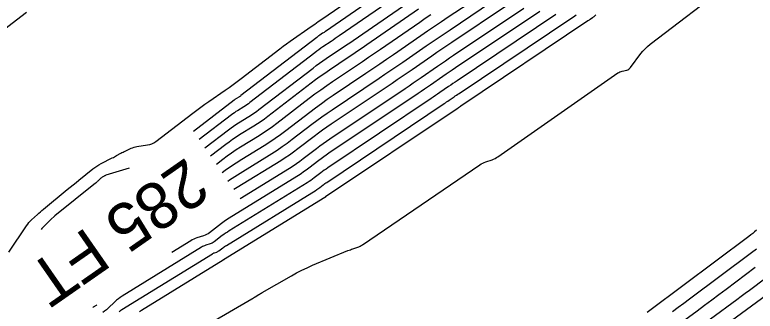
# Model space of a CAD drawing. Extents: x 1768942 to 1774819, y 723037 to 732099.
# Drawn here: x 1770796.8 to 1770891.8, y 726671.9 to 726709.8 of the extents above; entities that cross this region are included whole.
import ezdxf

# ---------------------------------------------------------------- set-up
doc = ezdxf.new("R2010")
doc.units = 0
doc.layers.add('R_Contour Annot', color=7, linetype='Continuous')
doc.layers.add('R_Contours', color=7, linetype='Continuous')

msp = doc.modelspace()

# ---------------------------------------------------------------- linework, layer by layer
at = {"layer": 'R_Contours'}
for points in [[(1770848.202, 726715.686), (1770836.674, 726707.725), (1770836.581, 726707.66), (1770836.487, 726707.597), (1770836.394, 726707.533), (1770836.3, 726707.47), (1770835.923, 726707.218), (1770835.829, 726707.154), (1770835.737, 726707.089), (1770835.645, 726707.022), (1770835.555, 726706.954), (1770825.81, 726699.484), (1770825.742, 726699.433), (1770825.673, 726699.385), (1770825.603, 726699.338), (1770825.531, 726699.292), (1770825.243, 726699.115), (1770825.172, 726699.07), (1770825.102, 726699.023), (1770825.033, 726698.974), (1770824.965, 726698.923), (1770819.726, 726694.907)], [(1770817.292, 726667.688), (1770827.207, 726673.444), (1770827.319, 726673.51), (1770827.431, 726673.577), (1770827.542, 726673.645), (1770827.653, 726673.714), (1770828.094, 726673.993), (1770828.204, 726674.063), (1770828.316, 726674.13), (1770828.428, 726674.197), (1770828.541, 726674.263), (1770832.288, 726676.405), (1770832.955, 726676.773), (1770833.633, 726677.12), (1770834.322, 726677.444), (1770835.021, 726677.748), (1770839.55, 726679.627), (1770839.704, 726679.69), (1770839.86, 726679.749), (1770840.017, 726679.805), (1770840.175, 726679.858), (1770840.809, 726680.064), (1770840.965, 726680.12), (1770841.115, 726680.188), (1770841.261, 726680.266), (1770841.401, 726680.354), (1770856.482, 726690.615), (1770856.661, 726690.729), (1770856.846, 726690.829), (1770857.037, 726690.918), (1770857.235, 726690.994), (1770858.039, 726691.273), (1770858.236, 726691.35), (1770858.427, 726691.439), (1770858.611, 726691.541), (1770858.789, 726691.656), (1770874.204, 726702.391), (1770874.329, 726702.47), (1770874.461, 726702.536), (1770874.598, 726702.589), (1770874.74, 726702.629), (1770875.323, 726702.765), (1770875.461, 726702.809), (1770875.586, 726702.875), (1770875.697, 726702.962), (1770875.794, 726703.071), (1770877.148, 726704.866), (1770877.413, 726705.195), (1770877.7, 726705.504), (1770878.006, 726705.793), (1770878.333, 726706.061), (1770888.553, 726713.898)], [(1770848.34, 726713.984), (1770838.439, 726707.145), (1770838.178, 726706.965), (1770837.916, 726706.787), (1770837.654, 726706.609), (1770837.391, 726706.433), (1770836.339, 726705.728), (1770836.077, 726705.55), (1770835.818, 726705.368), (1770835.563, 726705.181), (1770835.31, 726704.991), (1770826.962, 726698.592), (1770826.773, 726698.45), (1770826.58, 726698.314), (1770826.383, 726698.182), (1770826.183, 726698.056), (1770825.377, 726697.559), (1770825.177, 726697.433), (1770824.98, 726697.301), (1770824.787, 726697.164), (1770824.598, 726697.023), (1770820.461, 726693.852)], [(1770796.011, 726679.442), (1770798.302, 726682.824), (1770798.449, 726683.029), (1770798.607, 726683.224), (1770798.776, 726683.41), (1770798.956, 726683.587), (1770799.698, 726684.275), (1770799.885, 726684.445), (1770800.074, 726684.613), (1770800.266, 726684.777), (1770800.461, 726684.939), (1770803.526, 726687.44), (1770803.903, 726687.746), (1770804.279, 726688.052), (1770804.656, 726688.358), (1770805.034, 726688.662), (1770806.8, 726690.087), (1770807.055, 726690.281), (1770807.318, 726690.461), (1770807.591, 726690.627), (1770807.873, 726690.779), (1770809.312, 726691.505), (1770809.451, 726691.577), (1770809.589, 726691.649), (1770809.727, 726691.724), (1770809.863, 726691.8), (1770810.409, 726692.107), (1770810.546, 726692.183), (1770810.684, 726692.255), (1770810.824, 726692.325), (1770810.966, 726692.391), (1770811.735, 726692.742), (1770811.912, 726692.816), (1770812.094, 726692.877), (1770812.279, 726692.924), (1770812.468, 726692.959), (1770813.835, 726693.164), (1770814.119, 726693.225), (1770814.389, 726693.319), (1770814.645, 726693.448), (1770814.886, 726693.61), (1770819.632, 726697.247), (1770820.14, 726697.631), (1770820.652, 726698.009), (1770821.17, 726698.379), (1770821.692, 726698.743), (1770823.792, 726700.184), (1770824.315, 726700.547), (1770824.832, 726700.918), (1770825.345, 726701.295), (1770825.853, 726701.679), (1770830.801, 726705.472), (1770831.24, 726705.804), (1770831.683, 726706.132), (1770832.129, 726706.454), (1770832.579, 726706.771), (1770834.387, 726708.03), (1770834.839, 726708.345), (1770835.291, 726708.659), (1770835.743, 726708.974), (1770836.195, 726709.289), (1770840.941, 726712.591)], [(1770821.196, 726692.796), (1770824.231, 726695.122), (1770824.542, 726695.355), (1770824.859, 726695.579), (1770825.182, 726695.795), (1770825.51, 726696.003), (1770826.835, 726696.819), (1770827.164, 726697.027), (1770827.486, 726697.243), (1770827.804, 726697.467), (1770828.115, 726697.7), (1770835.065, 726703.027), (1770835.48, 726703.34), (1770835.9, 726703.646), (1770836.325, 726703.946), (1770836.754, 726704.238), (1770838.483, 726705.396), (1770838.915, 726705.686), (1770839.345, 726705.977), (1770839.775, 726706.27), (1770840.203, 726706.565), (1770848.479, 726712.281)], [(1770823.402, 726689.625), (1770823.806, 726689.926), (1770824.496, 726690.414), (1770825.197, 726690.884), (1770825.911, 726691.336), (1770828.791, 726693.109), (1770829.505, 726693.561), (1770830.206, 726694.031), (1770830.896, 726694.518), (1770831.573, 726695.024), (1770834.65, 726697.383), (1770835.391, 726697.941), (1770836.141, 726698.488), (1770836.899, 726699.022), (1770837.666, 726699.545), (1770841.866, 726702.356), (1770842.75, 726702.95), (1770843.632, 726703.548), (1770844.512, 726704.148), (1770845.39, 726704.752), (1770848.895, 726707.173), (1770849.773, 726707.777), (1770850.653, 726708.378), (1770851.535, 726708.975), (1770852.419, 726709.57), (1770855.965, 726711.945)], [(1770824.152, 726688.547), (1770824.369, 726688.701), (1770825.028, 726689.142), (1770825.698, 726689.567), (1770829.785, 726692.083), (1770830.458, 726692.509), (1770831.119, 726692.952), (1770831.769, 726693.411), (1770832.407, 726693.888), (1770834.936, 726695.827), (1770835.573, 726696.306), (1770836.216, 726696.775), (1770836.867, 726697.234), (1770837.526, 726697.683), (1770843.538, 726701.707), (1770844.301, 726702.22), (1770845.063, 726702.736), (1770845.822, 726703.255), (1770846.58, 726703.776), (1770849.607, 726705.867), (1770850.365, 726706.388), (1770851.125, 726706.907), (1770851.886, 726707.423), (1770852.649, 726707.936), (1770857.978, 726711.504)], [(1770860.04, 726711.097), (1770852.88, 726706.302), (1770852.237, 726705.87), (1770851.596, 726705.435), (1770850.957, 726704.999), (1770850.319, 726704.56), (1770847.77, 726702.8), (1770847.132, 726702.361), (1770846.493, 726701.924), (1770845.852, 726701.49), (1770845.209, 726701.058), (1770837.385, 726695.821), (1770836.835, 726695.446), (1770836.291, 726695.063), (1770835.754, 726694.671), (1770835.223, 726694.27), (1770833.11, 726692.651), (1770832.577, 726692.253), (1770832.034, 726691.869), (1770831.482, 726691.499), (1770830.92, 726691.143), (1770825.349, 726687.713), (1770824.921, 726687.443)], [(1770798.308, 726710.158), (1770797.554, 726709.588), (1770794.547, 726707.298)], [(1770864.165, 726710.283), (1770853.342, 726703.034), (1770852.94, 726702.764), (1770852.54, 726702.493), (1770852.141, 726702.22), (1770851.743, 726701.946), (1770850.151, 726700.847), (1770849.753, 726700.573), (1770849.354, 726700.301), (1770848.953, 726700.03), (1770848.552, 726699.76), (1770837.104, 726692.097), (1770836.771, 726691.87), (1770836.442, 726691.638), (1770836.116, 726691.4), (1770835.795, 726691.158), (1770834.515, 726690.177), (1770834.192, 726689.936), (1770833.864, 726689.704), (1770833.529, 726689.48), (1770833.189, 726689.264), (1770824.649, 726684.007), (1770824.312, 726683.793), (1770823.981, 726683.571), (1770823.655, 726683.341), (1770823.335, 726683.102), (1770821.784, 726681.913), (1770821.605, 726681.787), (1770821.416, 726681.679), (1770821.219, 726681.588), (1770821.013, 726681.514), (1770820.172, 726681.251), (1770819.964, 726681.18), (1770819.763, 726681.095), (1770819.566, 726680.999), (1770819.376, 726680.889), (1770816.967, 726679.406)], [(1770848.617, 726710.578), (1770841.967, 726705.985), (1770841.372, 726705.575), (1770840.774, 726705.168), (1770840.175, 726704.762), (1770839.575, 726704.358), (1770837.17, 726702.749), (1770836.572, 726702.342), (1770835.981, 726701.925), (1770835.397, 726701.499), (1770834.82, 726701.064), (1770829.268, 726696.808), (1770828.834, 726696.484), (1770828.393, 726696.172), (1770827.944, 726695.872), (1770827.487, 726695.582), (1770825.644, 726694.448), (1770825.187, 726694.158), (1770824.738, 726693.857), (1770824.297, 726693.545), (1770823.864, 726693.222), (1770821.93, 726691.74)], [(1770825.715, 726686.301), (1770832.054, 726690.204), (1770832.505, 726690.489), (1770832.949, 726690.786), (1770833.384, 726691.094), (1770833.812, 726691.414), (1770835.509, 726692.714), (1770835.935, 726693.036), (1770836.367, 726693.35), (1770836.803, 726693.658), (1770837.245, 726693.959), (1770846.881, 726700.409), (1770847.403, 726700.76), (1770847.923, 726701.113), (1770848.443, 726701.467), (1770848.961, 726701.824), (1770851.031, 726703.253), (1770851.549, 726703.61), (1770852.068, 726703.964), (1770852.589, 726704.317), (1770853.111, 726704.668), (1770862.103, 726710.69)], [(1770866.227, 726709.875), (1770853.572, 726701.4), (1770853.292, 726701.211), (1770853.012, 726701.022), (1770852.733, 726700.831), (1770852.454, 726700.64), (1770851.342, 726699.871), (1770851.063, 726699.68), (1770850.784, 726699.489), (1770850.504, 726699.299), (1770850.223, 726699.111), (1770836.964, 726690.235), (1770836.739, 726690.082), (1770836.517, 726689.925), (1770836.298, 726689.765), (1770836.081, 726689.602), (1770835.218, 726688.94), (1770835, 726688.778), (1770834.779, 726688.621), (1770834.553, 726688.47), (1770834.323, 726688.324), (1770824.299, 726682.153), (1770824.073, 726682.01), (1770823.851, 726681.861), (1770823.633, 726681.707), (1770823.419, 726681.547), (1770822.379, 726680.75), (1770822.259, 726680.666), (1770822.133, 726680.593), (1770822.001, 726680.532), (1770821.863, 726680.482), (1770821.299, 726680.307), (1770821.159, 726680.258), (1770821.024, 726680.202), (1770820.893, 726680.137), (1770820.765, 726680.064), (1770810.577, 726673.791), (1770810.329, 726673.629), (1770810.089, 726673.454), (1770809.859, 726673.268), (1770809.638, 726673.07), (1770808.773, 726672.251), (1770808.551, 726672.055), (1770808.318, 726671.873), (1770808.073, 726671.707)], [(1770810.182, 726671.827), (1770810.297, 726671.919), (1770810.416, 726672.006), (1770810.54, 726672.087), (1770822.154, 726679.238), (1770822.219, 726679.276), (1770822.286, 726679.309), (1770822.355, 726679.337), (1770822.425, 726679.362), (1770822.712, 726679.451), (1770822.782, 726679.476), (1770822.849, 726679.507), (1770822.913, 726679.544), (1770822.974, 726679.587), (1770823.502, 726679.992), (1770823.611, 726680.073), (1770823.722, 726680.152), (1770823.835, 726680.227), (1770823.95, 726680.3), (1770835.458, 726687.385), (1770835.577, 726687.46), (1770835.693, 726687.538), (1770835.808, 726687.619), (1770835.921, 726687.703), (1770836.367, 726688.045), (1770836.479, 726688.13), (1770836.593, 726688.213), (1770836.707, 726688.294), (1770836.824, 726688.373), (1770851.895, 726698.462), (1770852.055, 726698.569), (1770852.214, 726698.677), (1770852.373, 726698.786), (1770852.532, 726698.895), (1770853.166, 726699.333), (1770853.325, 726699.442), (1770853.484, 726699.551), (1770853.643, 726699.659), (1770853.803, 726699.766), (1770868.29, 726709.468), (1770868.479, 726709.595), (1770868.668, 726709.724), (1770868.856, 726709.852)], [(1770871.344, 726709.848), (1770871.142, 726709.639), (1770871.09, 726709.588), (1770871.036, 726709.54), (1770870.98, 726709.494), (1770870.921, 726709.452), (1770870.629, 726709.249), (1770870.56, 726709.202), (1770870.491, 726709.154), (1770870.422, 726709.108), (1770870.352, 726709.061), (1770854.034, 726698.132), (1770853.995, 726698.106), (1770853.956, 726698.079), (1770853.917, 726698.053), (1770853.878, 726698.026), (1770853.722, 726697.919), (1770853.684, 726697.892), (1770853.645, 726697.865), (1770853.606, 726697.839), (1770853.566, 726697.813), (1770836.683, 726686.511), (1770836.676, 726686.506), (1770836.668, 726686.5), (1770836.66, 726686.495), (1770836.653, 726686.489), (1770836.623, 726686.466), (1770836.616, 726686.461), (1770836.608, 726686.455), (1770836.601, 726686.45), (1770836.593, 726686.445), (1770823.6, 726678.446), (1770823.593, 726678.442), (1770823.586, 726678.437), (1770823.569, 726678.424), (1770823.565, 726678.421), (1770823.561, 726678.42), (1770823.55, 726678.416), (1770823.545, 726678.414), (1770823.543, 726678.413), (1770813.05, 726671.952), (1770812.797, 726671.795)], [(1770850.18, 726709.851), (1770849.467, 726709.364), (1770848.755, 726708.875), (1770843.732, 726705.406), (1770842.968, 726704.88), (1770842.203, 726704.358), (1770841.436, 726703.838), (1770840.667, 726703.321), (1770837.586, 726701.259), (1770836.82, 726700.737), (1770836.063, 726700.204), (1770835.315, 726699.658), (1770834.575, 726699.1), (1770830.42, 726695.916), (1770829.865, 726695.501), (1770829.3, 726695.102), (1770828.724, 726694.716), (1770828.139, 726694.346), (1770825.778, 726692.892), (1770825.192, 726692.521), (1770824.617, 726692.136), (1770824.052, 726691.736), (1770823.496, 726691.321), (1770822.665, 726690.684)], [(1770811.478, 726690.206), (1770808.493, 726689.276), (1770808.429, 726689.254), (1770808.367, 726689.227), (1770808.306, 726689.197), (1770808.247, 726689.164), (1770808.015, 726689.021), (1770807.958, 726688.984), (1770807.903, 726688.944), (1770807.85, 726688.901), (1770807.8, 726688.856), (1770807.46, 726688.535), (1770807.387, 726688.466), (1770807.312, 726688.4), (1770807.235, 726688.334), (1770807.158, 726688.27), (1770801.952, 726684.074), (1770801.362, 726683.571), (1770800.805, 726683.035), (1770800.281, 726682.467), (1770800.177, 726682.341)], [(1770891.991, 726682.231), (1770891.742, 726682.035), (1770891.491, 726681.841), (1770891.24, 726681.648), (1770890.987, 726681.457), (1770878.284, 726671.949), (1770877.96, 726671.707)], [(1770881.204, 726671.831), (1770881.932, 726672.37), (1770882.659, 726672.909), (1770883.384, 726673.451), (1770891.339, 726679.405), (1770891.964, 726679.876)], [(1770891.827, 726677.455), (1770888.098, 726674.664), (1770887.165, 726673.967), (1770886.231, 726673.273), (1770885.294, 726672.581), (1770884.356, 726671.891), (1770879.028, 726667.98)], [(1770879.325, 726665.945), (1770889.461, 726673.384), (1770889.997, 726673.778), (1770890.531, 726674.173), (1770891.065, 726674.57), (1770891.597, 726674.967), (1770893.726, 726676.56)], [(1770894.566, 726674.878), (1770879.622, 726663.91)], [(1770807.325, 726672.696), (1770807.221, 726672.615), (1770806.855, 726672.365), (1770806.827, 726672.349)]]:
    msp.add_lwpolyline(points, dxfattribs=at)

# ---------------------------------------------------------------- texts
at = {"layer": 'R_Contour Annot'}
msp.add_text('285 FT', height=6, rotation=214.83534, dxfattribs=at).set_placement((1770818.839, 726691.674))

doc.saveas('drawing.dxf')
